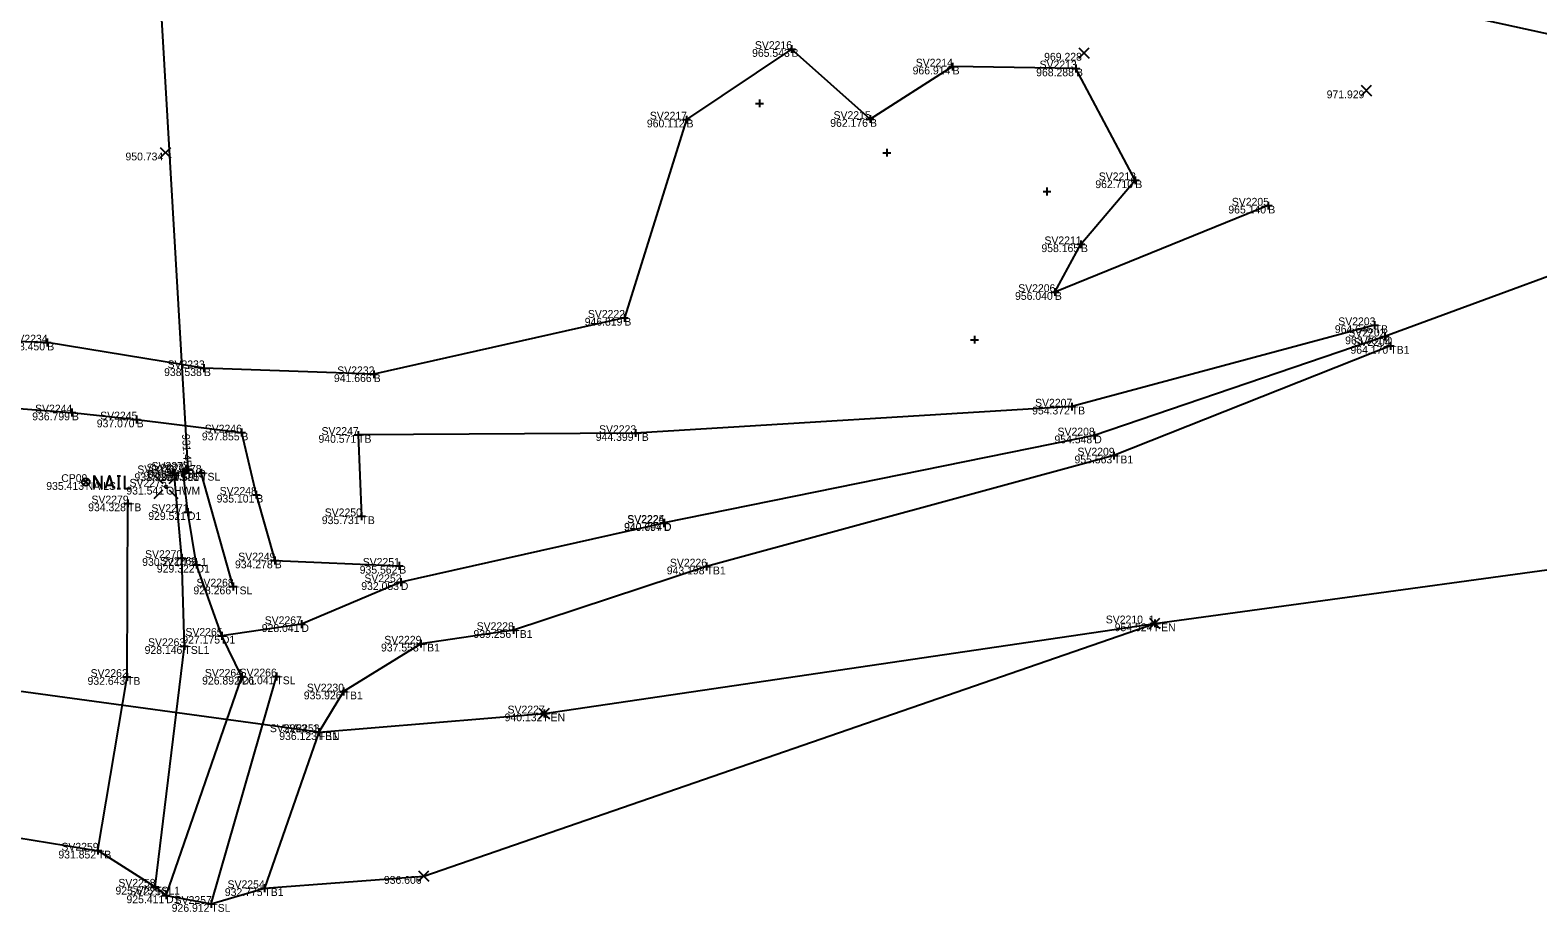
# Model space of a CAD drawing. Extents: x 2065431 to 2068157, y 709104 to 709719.
# Drawn here: x 2066392 to 2066585.2, y 709255 to 709367.9 of the extents above; entities that cross this region are included whole.
import ezdxf

# ---------------------------------------------------------------- set-up
doc = ezdxf.new("R2010")
doc.units = 0
for name, color, linetype in [('_CIVIL_CONSTRUCTION', 7, 'Continuous'), ('DR_X_Storm_Sewer', 7, 'Continuous'), ('DT_X_Terrain_Boundary', 7, 'Continuous'), ('RD_X_Fence', 7, 'Continuous'), ('RS_Raster1', 7, 'Continuous'), ('RW_X_CL_100_Bearings', 7, 'Continuous'), ('RW_X_CL_100_Stations', 7, 'Continuous'), ('RW_X_Fee_WL', 7, 'Continuous'), ('SC_Scratch1', 7, 'Continuous'), ('SV_X_Break_Lines', 7, 'Continuous'), ('SV_X_Mon_Cells_Found', 7, 'Continuous'), ('SV_X_Text_Elevation', 7, 'Continuous'), ('SV_X_Text_Name', 7, 'Continuous'), ('SV_X_Toe_of_Slope', 7, 'Continuous'), ('SV_X_Top_of_Bank', 7, 'Continuous')]:
    doc.layers.add(name, color=color, linetype=linetype)

msp = doc.modelspace()

# ---------------------------------------------------------------- linework, layer by layer
at = {"layer": '_CIVIL_CONSTRUCTION'}
for p, q in [((2066411.71, 709311.61), (2066412.71, 709311.61)), ((2066412.21, 709312.11), (2066412.21, 709311.11)), ((2066412.21, 709311.61), (2066412.21, 709311.61))]:
    msp.add_line(p, q, dxfattribs=at)
at = {"layer": 'DR_X_Storm_Sewer'}
msp.add_line((2066393.36, 709634.39), (2066412.21, 709311.61), dxfattribs=at)
at = {"layer": 'DT_X_Terrain_Boundary'}
msp.add_lwpolyline([(2066248.51, 709424.93), (2066307.45, 709345.95), (2066304.08, 709329.83), (2066357.5, 709287.59), (2066388.19, 709264.84), (2066400.73, 709262.78), (2066407.99, 709258.2), (2066409.41, 709257.09), (2066415.2, 709255.99), (2066422, 709258.01), (2066442.41, 709259.57), (2066536.08, 709291.94), (2066609.07, 709301.93)], dxfattribs=at)
at = {"layer": 'RD_X_Fence'}
msp.add_line((2066428.96, 709278), (2066357.61, 709287.76), dxfattribs=at)
msp.add_lwpolyline([(2066428.96, 709278), (2066457.85, 709280.4), (2066536.08, 709291.94), (2066609.07, 709301.93), (2066640.16, 709306.98)], dxfattribs=at)
at = {"layer": 'RS_Raster1'}
for p, q in [((2066489.55, 709366.03), (2066489.55, 709365.03)), ((2066489.05, 709365.53), (2066490.05, 709365.53)), ((2066489.55, 709365.53), (2066489.55, 709365.53)), ((2066510.18, 709363.78), (2066510.18, 709362.78)), ((2066509.68, 709363.28), (2066510.68, 709363.28)), ((2066510.18, 709363.28), (2066510.18, 709363.28)), ((2066525.49, 709363.04), (2066526.49, 709363.04)), ((2066525.99, 709363.54), (2066525.99, 709362.54)), ((2066525.99, 709363.04), (2066525.99, 709363.04)), ((2066484.94, 709358.56), (2066485.94, 709358.56)), ((2066485.44, 709359.06), (2066485.44, 709358.06)), ((2066485.44, 709358.56), (2066485.44, 709358.56)), ((2066475.59, 709356.49), (2066476.59, 709356.49)), ((2066476.09, 709356.99), (2066476.09, 709355.99)), ((2066476.09, 709356.49), (2066476.09, 709356.49)), ((2066499.1, 709356.56), (2066500.1, 709356.56)), ((2066499.6, 709357.06), (2066499.6, 709356.06)), ((2066499.6, 709356.56), (2066499.6, 709356.56)), ((2066501.25, 709352.24), (2066502.25, 709352.24)), ((2066501.75, 709352.74), (2066501.75, 709351.74)), ((2066501.75, 709352.24), (2066501.75, 709352.24)), ((2066533.09, 709348.71), (2066534.09, 709348.71)), ((2066533.59, 709349.21), (2066533.59, 709348.21)), ((2066533.59, 709348.71), (2066533.59, 709348.71)), ((2066521.77, 709347.27), (2066522.77, 709347.27)), ((2066522.27, 709347.77), (2066522.27, 709346.77)), ((2066522.27, 709347.27), (2066522.27, 709347.27)), ((2066550.13, 709345.46), (2066551.13, 709345.46)), ((2066550.63, 709345.96), (2066550.63, 709344.96)), ((2066550.63, 709345.46), (2066550.63, 709345.46)), ((2066526.63, 709341.01), (2066526.63, 709340.01)), ((2066526.13, 709340.51), (2066527.13, 709340.51)), ((2066526.63, 709340.51), (2066526.63, 709340.51)), ((2066523.29, 709334.89), (2066523.29, 709333.89)), ((2066522.79, 709334.39), (2066523.79, 709334.39)), ((2066523.29, 709334.39), (2066523.29, 709334.39)), ((2066467.62, 709331.09), (2066468.62, 709331.09)), ((2066468.12, 709331.59), (2066468.12, 709330.59)), ((2066468.12, 709331.09), (2066468.12, 709331.09)), ((2066563.76, 709330.14), (2066564.76, 709330.14)), ((2066564.26, 709330.64), (2066564.26, 709329.64)), ((2066564.26, 709330.14), (2066564.26, 709330.14)), ((2066565.56, 709329.2), (2066565.56, 709328.2)), ((2066393.68, 709327.92), (2066394.68, 709327.92)), ((2066394.18, 709328.42), (2066394.18, 709327.42)), ((2066394.18, 709327.92), (2066394.18, 709327.92)), ((2066512.48, 709328.28), (2066513.48, 709328.28)), ((2066512.98, 709328.78), (2066512.98, 709327.78)), ((2066512.98, 709328.28), (2066512.98, 709328.28)), ((2066565.06, 709328.7), (2066566.06, 709328.7)), ((2066565.56, 709328.7), (2066565.56, 709328.7)), ((2066565.77, 709327.49), (2066566.77, 709327.49)), ((2066566.27, 709327.99), (2066566.27, 709326.99)), ((2066566.27, 709327.49), (2066566.27, 709327.49)), ((2066414.25, 709325.13), (2066414.25, 709324.13)), ((2066413.75, 709324.63), (2066414.75, 709324.63)), ((2066414.25, 709324.63), (2066414.25, 709324.63)), ((2066435.51, 709323.86), (2066436.51, 709323.86)), ((2066436.01, 709324.36), (2066436.01, 709323.36)), ((2066436.01, 709323.86), (2066436.01, 709323.86)), ((2066397.34, 709319.46), (2066397.34, 709318.46)), ((2066524.95, 709319.71), (2066525.95, 709319.71)), ((2066525.45, 709320.21), (2066525.45, 709319.21)), ((2066525.45, 709319.71), (2066525.45, 709319.71)), ((2066396.84, 709318.96), (2066397.84, 709318.96)), ((2066397.34, 709318.96), (2066397.34, 709318.96)), ((2066405.13, 709318.06), (2066406.13, 709318.06)), ((2066405.63, 709318.56), (2066405.63, 709317.56)), ((2066405.63, 709318.06), (2066405.63, 709318.06)), ((2066418.56, 709316.39), (2066419.56, 709316.39)), ((2066419.06, 709316.89), (2066419.06, 709315.89)), ((2066419.06, 709316.39), (2066419.06, 709316.39)), ((2066433.51, 709316.08), (2066434.51, 709316.08)), ((2066434.01, 709316.58), (2066434.01, 709315.58)), ((2066434.01, 709316.08), (2066434.01, 709316.08)), ((2066469.04, 709316.32), (2066470.04, 709316.32)), ((2066469.54, 709316.82), (2066469.54, 709315.82)), ((2066469.54, 709316.32), (2066469.54, 709316.32)), ((2066527.83, 709316.01), (2066528.83, 709316.01)), ((2066528.33, 709316.51), (2066528.33, 709315.51)), ((2066528.33, 709316.01), (2066528.33, 709316.01)), ((2066530.86, 709313.94), (2066530.86, 709312.94)), ((2066410.43, 709311.67), (2066410.43, 709310.67)), ((2066411.47, 709311.62), (2066412.47, 709311.62)), ((2066411.61, 709311.89), (2066411.61, 709310.89)), ((2066411.73, 709311.68), (2066412.73, 709311.68)), ((2066411.97, 709312.12), (2066411.97, 709311.12)), ((2066411.97, 709311.62), (2066411.97, 709311.62)), ((2066412.23, 709312.18), (2066412.23, 709311.18)), ((2066412.23, 709311.68), (2066412.23, 709311.68)), ((2066413.89, 709311.73), (2066413.89, 709310.73)), ((2066530.36, 709313.44), (2066531.36, 709313.44)), ((2066530.86, 709313.44), (2066530.86, 709313.44)), ((2066409.93, 709311.17), (2066410.93, 709311.17)), ((2066410.43, 709311.17), (2066410.43, 709311.17)), ((2066411.11, 709311.39), (2066412.11, 709311.39)), ((2066411.61, 709311.39), (2066411.61, 709311.39)), ((2066413.39, 709311.23), (2066414.39, 709311.23)), ((2066413.89, 709311.23), (2066413.89, 709311.23)), ((2066404.52, 709307.81), (2066404.52, 709306.81)), ((2066420.46, 709308.42), (2066421.46, 709308.42)), ((2066420.96, 709308.92), (2066420.96, 709307.92)), ((2066420.96, 709308.42), (2066420.96, 709308.42)), ((2066404.02, 709307.31), (2066405.02, 709307.31)), ((2066404.52, 709307.31), (2066404.52, 709307.31)), ((2066411.7, 709306.2), (2066412.7, 709306.2)), ((2066412.2, 709306.7), (2066412.2, 709305.7)), ((2066412.2, 709306.2), (2066412.2, 709306.2)), ((2066434.44, 709306.16), (2066434.44, 709305.16)), ((2066433.94, 709305.66), (2066434.94, 709305.66)), ((2066434.44, 709305.66), (2066434.44, 709305.66)), ((2066472.68, 709304.77), (2066473.68, 709304.77)), ((2066472.71, 709304.82), (2066473.71, 709304.82)), ((2066473.18, 709305.27), (2066473.18, 709304.27)), ((2066473.18, 709304.77), (2066473.18, 709304.77)), ((2066473.21, 709305.32), (2066473.21, 709304.32)), ((2066473.21, 709304.82), (2066473.21, 709304.82)), ((2066410.92, 709300.31), (2066411.92, 709300.31)), ((2066411.42, 709300.81), (2066411.42, 709299.81)), ((2066411.42, 709300.31), (2066411.42, 709300.31)), ((2066422.83, 709300), (2066423.83, 709300)), ((2066423.33, 709300.5), (2066423.33, 709299.5)), ((2066423.33, 709300), (2066423.33, 709300)), ((2066412.8, 709299.45), (2066413.8, 709299.45)), ((2066413.3, 709299.95), (2066413.3, 709298.95)), ((2066413.3, 709299.45), (2066413.3, 709299.45)), ((2066438.78, 709299.31), (2066439.78, 709299.31)), ((2066439.28, 709299.81), (2066439.28, 709298.81)), ((2066439.28, 709299.31), (2066439.28, 709299.31)), ((2066478.16, 709299.22), (2066479.16, 709299.22)), ((2066478.66, 709299.72), (2066478.66, 709298.72)), ((2066478.66, 709299.22), (2066478.66, 709299.22)), ((2066417.5, 709296.66), (2066418.5, 709296.66)), ((2066418, 709297.16), (2066418, 709296.16)), ((2066418, 709296.66), (2066418, 709296.66)), ((2066438.98, 709297.22), (2066439.98, 709297.22)), ((2066439.48, 709297.72), (2066439.48, 709296.72)), ((2066439.48, 709297.22), (2066439.48, 709297.22)), ((2066426.74, 709292.34), (2066426.74, 709291.34)), ((2066536.08, 709292.44), (2066536.08, 709291.44)), ((2066416.05, 709290.35), (2066417.05, 709290.35)), ((2066416.55, 709290.85), (2066416.55, 709289.85)), ((2066416.55, 709290.35), (2066416.55, 709290.35)), ((2066426.24, 709291.84), (2066427.24, 709291.84)), ((2066426.74, 709291.84), (2066426.74, 709291.84)), ((2066453.4, 709291.08), (2066454.4, 709291.08)), ((2066453.9, 709291.58), (2066453.9, 709290.58)), ((2066453.9, 709291.08), (2066453.9, 709291.08)), ((2066535.58, 709291.94), (2066536.58, 709291.94)), ((2066536.08, 709291.94), (2066536.08, 709291.94)), ((2066411.25, 709289.03), (2066412.25, 709289.03)), ((2066411.75, 709289.53), (2066411.75, 709288.53)), ((2066411.75, 709289.03), (2066411.75, 709289.03)), ((2066441.54, 709289.34), (2066442.54, 709289.34)), ((2066442.04, 709289.84), (2066442.04, 709288.84)), ((2066442.04, 709289.34), (2066442.04, 709289.34)), ((2066403.9, 709285.07), (2066404.9, 709285.07)), ((2066404.4, 709285.57), (2066404.4, 709284.57)), ((2066404.4, 709285.07), (2066404.4, 709285.07)), ((2066418.59, 709285.1), (2066419.59, 709285.1)), ((2066419.09, 709285.6), (2066419.09, 709284.6)), ((2066419.09, 709285.1), (2066419.09, 709285.1)), ((2066423.03, 709285.14), (2066424.03, 709285.14)), ((2066423.53, 709285.64), (2066423.53, 709284.64)), ((2066423.53, 709285.14), (2066423.53, 709285.14)), ((2066431.65, 709283.21), (2066432.65, 709283.21)), ((2066432.15, 709283.71), (2066432.15, 709282.71)), ((2066432.15, 709283.21), (2066432.15, 709283.21)), ((2066457.85, 709280.9), (2066457.85, 709279.9)), ((2066457.35, 709280.4), (2066458.35, 709280.4)), ((2066457.85, 709280.4), (2066457.85, 709280.4)), ((2066428.46, 709278), (2066429.46, 709278)), ((2066428.46, 709278), (2066429.46, 709278)), ((2066428.96, 709278.5), (2066428.96, 709277.5)), ((2066428.96, 709278.5), (2066428.96, 709277.5)), ((2066428.96, 709278), (2066428.96, 709278)), ((2066428.96, 709278), (2066428.96, 709278)), ((2066400.67, 709263.32), (2066400.67, 709262.32)), ((2066400.17, 709262.82), (2066401.17, 709262.82)), ((2066400.67, 709262.82), (2066400.67, 709262.82)), ((2066407.49, 709258.2), (2066408.49, 709258.2)), ((2066407.99, 709258.7), (2066407.99, 709257.7)), ((2066407.99, 709258.2), (2066407.99, 709258.2)), ((2066409.41, 709257.59), (2066409.41, 709256.59)), ((2066421.5, 709258.01), (2066422.5, 709258.01)), ((2066422, 709258.51), (2066422, 709257.51)), ((2066422, 709258.01), (2066422, 709258.01)), ((2066408.91, 709257.09), (2066409.91, 709257.09)), ((2066409.41, 709257.09), (2066409.41, 709257.09)), ((2066414.7, 709255.99), (2066415.7, 709255.99)), ((2066415.2, 709256.49), (2066415.2, 709255.49)), ((2066415.2, 709255.99), (2066415.2, 709255.99))]:
    msp.add_line(p, q, dxfattribs=at)
at = {"layer": 'RW_X_CL_100_Bearings'}
for p, q in [((2066526.34, 709364.37), (2066527.67, 709365.7)), ((2066526.34, 709365.7), (2066527.67, 709364.37)), ((2066562.52, 709359.55), (2066563.86, 709360.89)), ((2066562.52, 709360.89), (2066563.86, 709359.55)), ((2066408.66, 709351.59), (2066409.99, 709352.92)), ((2066408.66, 709352.92), (2066409.99, 709351.59)), ((2066535.41, 709291.27), (2066536.74, 709292.61)), ((2066535.41, 709292.61), (2066536.74, 709291.27)), ((2066457.18, 709279.73), (2066458.52, 709281.06)), ((2066457.18, 709281.06), (2066458.52, 709279.73)), ((2066441.74, 709258.9), (2066443.08, 709260.24)), ((2066441.74, 709260.24), (2066443.08, 709258.9))]:
    msp.add_line(p, q, dxfattribs=at)
at = {"layer": 'RW_X_CL_100_Stations'}
for p, q in [((2066398.76, 709310.41), (2066399.47, 709309.7)), ((2066398.76, 709309.7), (2066399.47, 709310.41)), ((2066407.88, 709310.95), (2066408.97, 709309.86)), ((2066409.8, 709309.86), (2066410.9, 709310.95)), ((2066407.88, 709307.93), (2066408.97, 709309.03)), ((2066409.8, 709309.03), (2066410.9, 709307.93))]:
    msp.add_line(p, q, dxfattribs=at)
for points in [[(2066400.2, 709309.24), (2066400.2, 709310.84), (2066401.15, 709309.24), (2066401.15, 709310.84)], [(2066401.65, 709309.24), (2066402.16, 709310.84), (2066402.65, 709309.24)], [(2066403.15, 709310.84), (2066403.56, 709310.84)], [(2066403.35, 709309.24), (2066403.35, 709310.84)], [(2066404.06, 709310.84), (2066404.06, 709309.24), (2066404.93, 709309.24)], [(2066402.52, 709309.62), (2066401.78, 709309.62)], [(2066403.15, 709309.24), (2066403.56, 709309.24)]]:
    msp.add_lwpolyline(points, dxfattribs=at)
for centre, radius in [((2066399.11, 709310.05), 0.5), ((2066409.39, 709309.45), 0.17)]:
    msp.add_circle(centre, radius, dxfattribs=at)
at = {"layer": 'RW_X_Fee_WL'}
for points in [[(2066667.37, 709347.27), (2066641.36, 709347.76), (2066602.25, 709342.21), (2066565.56, 709328.7), (2066528.33, 709316.01), (2066473.21, 709304.82), (2066473.18, 709304.77), (2066439.48, 709297.22), (2066426.74, 709291.84), (2066416.55, 709290.35)], [(2066409.41, 709257.09), (2066419.09, 709285.1), (2066416.55, 709290.35), (2066413.3, 709299.45), (2066412.2, 709306.2), (2066411.61, 709311.39)]]:
    msp.add_lwpolyline(points, dxfattribs=at)
at = {"layer": 'SV_X_Break_Lines'}
for points in [[(2066296.29, 709410.91), (2066340.48, 709404.99), (2066380.77, 709397.8), (2066419, 709392.82), (2066478.03, 709384.6), (2066527.44, 709376.82), (2066563.6, 709372.51), (2066611.9, 709361.92)], [(2066550.63, 709345.46), (2066523.29, 709334.39), (2066526.63, 709340.51), (2066533.59, 709348.71), (2066525.99, 709363.04), (2066510.18, 709363.28), (2066499.6, 709356.56), (2066489.55, 709365.53), (2066476.09, 709356.49), (2066468.12, 709331.09), (2066436.01, 709323.86), (2066414.25, 709324.63), (2066394.18, 709327.92), (2066366.48, 709328.76)], [(2066380.26, 709320.24), (2066397.34, 709318.96), (2066405.63, 709318.06), (2066419.06, 709316.39), (2066420.96, 709308.42), (2066423.33, 709300), (2066439.28, 709299.31)]]:
    msp.add_lwpolyline(points, dxfattribs=at)
at = {"layer": 'SV_X_Toe_of_Slope'}
for points in [[(2066407.99, 709258.2), (2066411.75, 709289.03), (2066411.42, 709300.31), (2066410.43, 709311.17)], [(2066418, 709296.66), (2066413.89, 709311.23)], [(2066415.2, 709255.99), (2066423.53, 709285.14)]]:
    msp.add_lwpolyline(points, dxfattribs=at)
at = {"layer": 'SV_X_Top_of_Bank'}
for points in [[(2066564.26, 709330.14), (2066525.45, 709319.71), (2066469.54, 709316.32), (2066434.01, 709316.08), (2066434.44, 709305.66)], [(2066566.27, 709327.49), (2066530.86, 709313.44), (2066478.66, 709299.22), (2066453.9, 709291.08), (2066442.04, 709289.34), (2066432.15, 709283.21), (2066428.96, 709278), (2066422, 709258.01)], [(2066400.67, 709262.82), (2066404.4, 709285.07), (2066404.52, 709307.31)]]:
    msp.add_lwpolyline(points, dxfattribs=at)

# ---------------------------------------------------------------- texts
at = {"layer": 'SC_Scratch1'}
msp.add_text("931.45'", height=1, rotation=273.3419, dxfattribs=at).set_placement((2066411.44, 709316.17))
at = {"layer": 'SV_X_Mon_Cells_Found'}
for s, p in [('SV2216', (2066484.85, 709365.53)), ('SV2214', (2066505.46, 709363.28)), ('SV2213', (2066521.33, 709363.04)), ('SV2217', (2066471.39, 709356.49)), ('SV2215', (2066494.93, 709356.56)), ('SV2212', (2066528.91, 709348.71)), ('SV2205', (2066545.96, 709345.46)), ('SV2211', (2066521.95, 709340.51)), ('SV2206', (2066518.59, 709334.39)), ('SV2222', (2066463.45, 709331.09)), ('SV2203', (2066559.6, 709330.14)), ('SV2202', (2066560.89, 709328.7)), ('SV2234', (2066389.46, 709327.92)), ('SV2204', (2066561.55, 709327.49)), ('SV2233', (2066409.59, 709324.63)), ('SV2232', (2066431.34, 709323.86)), ('SV2244', (2066392.62, 709318.96)), ('SV2207', (2066520.75, 709319.71)), ('SV2245', (2066400.96, 709318.06)), ('SV2246', (2066414.36, 709316.39)), ('SV2247', (2066429.32, 709316.08)), ('SV2223', (2066464.88, 709316.32)), ('SV2208', (2066523.63, 709316.01)), ('SV2209', (2066526.18, 709313.44)), ('SV2276', (2066405.72, 709311.17)), ('SV2277', (2066406.91, 709311.39)), ('SV2272', (2066407.54, 709311.61)), ('SV2278', (2066409.19, 709311.23)), ('CP09', (2066395.97, 709310.05)), ('SV2275', (2066404.72, 709309.45)), ('SV2279', (2066399.84, 709307.31)), ('SV2248', (2066416.27, 709308.42)), ('SV2271', (2066407.52, 709306.2)), ('SV2250', (2066429.73, 709305.66)), ('SV2224', (2066468.49, 709304.82)), ('SV2225', (2066468.51, 709304.77)), ('SV2270', (2066406.71, 709300.31)), ('SV2269', (2066408.61, 709299.45)), ('SV2249', (2066418.65, 709300)), ('SV2251', (2066434.6, 709299.31)), ('SV2226', (2066473.96, 709299.22)), ('SV2252', (2066434.81, 709297.22)), ('SV2268', (2066413.3, 709296.66)), ('SV2267', (2066422.04, 709291.84)), ('SV2210_1', (2066529.81, 709291.94)), ('SV2265', (2066411.88, 709290.35)), ('SV2229', (2066437.36, 709289.34)), ('SV2228', (2066449.2, 709291.08)), ('SV2263', (2066407.09, 709289.03)), ('SV2262', (2066399.73, 709285.07)), ('SV2264', (2066414.37, 709285.1)), ('SV2266', (2066418.83, 709285.14)), ('SV2230', (2066427.44, 709283.21)), ('SV2227', (2066453.16, 709280.4)), ('SV2253_1', (2066422.7, 709278)), ('SV2253', (2066424.3, 709278)), ('SV2259', (2066395.99, 709262.82)), ('SV2258', (2066403.29, 709258.2)), ('SV2256', (2066404.71, 709257.09)), ('SV2254', (2066417.28, 709258.01)), ('SV2257', (2066410.5, 709255.99))]:
    msp.add_text(s, height=1, dxfattribs=at).set_placement(p)
at = {"layer": 'SV_X_Text_Elevation'}
for s, p in [('B', (2066489.55, 709364.53)), ('B', (2066510.18, 709362.28)), ('B', (2066525.99, 709362.04)), ('B', (2066476.09, 709355.49)), ('B', (2066499.6, 709355.56)), ('B', (2066533.59, 709347.71)), ('B', (2066550.63, 709344.46)), ('B', (2066526.63, 709339.51)), ('B', (2066523.29, 709333.39)), ('B', (2066468.12, 709330.09)), ('TB', (2066564.26, 709329.14)), ('B', (2066394.18, 709326.92)), ('D', (2066565.56, 709327.7)), ('TB1', (2066566.27, 709326.49)), ('B', (2066414.25, 709323.63)), ('B', (2066436.01, 709322.86)), ('TB', (2066525.45, 709318.71)), ('B', (2066397.34, 709317.96)), ('B', (2066405.63, 709317.06)), ('B', (2066419.06, 709315.39)), ('TB', (2066434.01, 709315.08)), ('TB', (2066469.54, 709315.32)), ('D', (2066528.33, 709315.01)), ('PIO', (2066412.21, 709310.61)), ('TB1', (2066530.86, 709312.44)), ('NAILS', (2066399.11, 709309.05)), ('TSL1', (2066410.43, 709310.17)), ('D1', (2066411.61, 709310.39)), ('TSL', (2066413.89, 709310.23)), ('OHWM', (2066409.39, 709308.45)), ('B', (2066420.96, 709307.42)), ('TB', (2066404.52, 709306.31)), ('D1', (2066412.2, 709305.2)), ('TB', (2066434.44, 709304.66)), ('D', (2066473.18, 709303.77)), ('D', (2066473.21, 709303.82)), ('TSL1', (2066411.42, 709299.31)), ('B', (2066423.33, 709299)), ('D1', (2066413.3, 709298.45)), ('B', (2066439.28, 709298.31)), ('TB1', (2066478.66, 709298.22)), ('TSL', (2066418, 709295.66)), ('D', (2066439.48, 709296.22)), ('D1', (2066416.55, 709289.35)), ('D', (2066426.74, 709290.84)), ('TB1', (2066453.9, 709290.08)), ('FEN', (2066536.08, 709290.94)), ('TSL1', (2066411.75, 709288.03)), ('TB1', (2066442.04, 709288.34)), ('TB', (2066404.4, 709284.07)), ('D1', (2066419.09, 709284.1)), ('TSL', (2066423.53, 709284.14)), ('TB1', (2066432.15, 709282.21)), ('FEN', (2066457.85, 709279.4)), ('TB1', (2066428.96, 709277)), ('FEN', (2066428.96, 709277)), ('TB', (2066400.67, 709261.82)), ('TSL1', (2066407.99, 709257.2)), ('TB1', (2066422, 709257.01)), ('D1', (2066409.41, 709256.09)), ('TSL', (2066415.2, 709254.99))]:
    msp.add_text(s, height=1, dxfattribs=at).set_placement(p)
at = {"layer": 'SV_X_Text_Name'}
for s, p in [('965.543', (2066484.49, 709364.53)), ('969.228', (2066521.91, 709364.04)), ('966.914', (2066505.06, 709362.28)), ('968.288', (2066520.89, 709362.04)), ('971.929', (2066558.11, 709359.22)), ('960.112', (2066471.01, 709355.49)), ('962.176', (2066494.5, 709355.56)), ('950.734', (2066404.2, 709351.26)), ('962.710', (2066528.47, 709347.71)), ('965.140', (2066545.51, 709344.46)), ('958.165', (2066521.56, 709339.51)), ('956.040', (2066518.18, 709333.39)), ('946.819', (2066463.04, 709330.09)), ('964.646', (2066559.16, 709329.14)), ('938.450', (2066389.06, 709326.92)), ('963.361', (2066560.48, 709327.7)), ('964.170', (2066561.16, 709326.49)), ('938.538', (2066409.15, 709323.63)), ('941.666', (2066430.91, 709322.86)), ('954.372', (2066520.37, 709318.71)), ('936.799', (2066392.25, 709317.96)), ('937.070', (2066400.52, 709317.06)), ('937.855', (2066413.99, 709315.39)), ('940.571', (2066428.93, 709315.08)), ('944.399', (2066464.46, 709315.32)), ('954.548', (2066523.23, 709315.01)), ('931.446', (2066407.1, 709310.61)), ('955.563', (2066525.8, 709312.44)), ('935.413', (2066394.05, 709309.05)), ('931.329', (2066405.34, 709310.17)), ('930.571', (2066406.53, 709310.39)), ('931.595', (2066408.82, 709310.23)), ('931.541', (2066404.31, 709308.45)), ('935.101', (2066415.88, 709307.42)), ('934.328', (2066399.42, 709306.31)), ('929.521', (2066407.12, 709305.2)), ('935.731', (2066429.36, 709304.66)), ('940.697', (2066468.08, 709303.77)), ('940.704', (2066468.09, 709303.82)), ('930.221', (2066406.34, 709299.31)), ('934.278', (2066418.23, 709299)), ('929.322', (2066408.22, 709298.45)), ('935.562', (2066434.21, 709298.31)), ('943.198', (2066473.56, 709298.22)), ('928.266', (2066412.9, 709295.66)), ('932.053', (2066434.41, 709296.22)), ('927.175', (2066411.48, 709289.35)), ('928.041', (2066421.66, 709290.84)), ('939.256', (2066448.79, 709290.08)), ('954.524', (2066530.95, 709290.94)), ('954.524', (2066530.95, 709290.94)), ('928.146', (2066406.65, 709288.03)), ('937.558', (2066436.94, 709288.34)), ('932.643', (2066399.34, 709284.07)), ('926.892', (2066414.02, 709284.1)), ('926.041', (2066418.45, 709284.14)), ('935.926', (2066427.05, 709282.21)), ('940.132', (2066452.78, 709279.4)), ('940.132', (2066452.78, 709279.4)), ('936.123', (2066423.9, 709277)), ('936.123', (2066423.9, 709277)), ('931.852', (2066395.6, 709261.82)), ('936.606', (2066437.31, 709258.57)), ('925.675', (2066402.92, 709257.2)), ('932.775', (2066416.93, 709257.01)), ('925.411', (2066404.33, 709256.09)), ('926.912', (2066410.12, 709254.99))]:
    msp.add_text(s, height=1, dxfattribs=at).set_placement(p)

doc.saveas('drawing.dxf')
